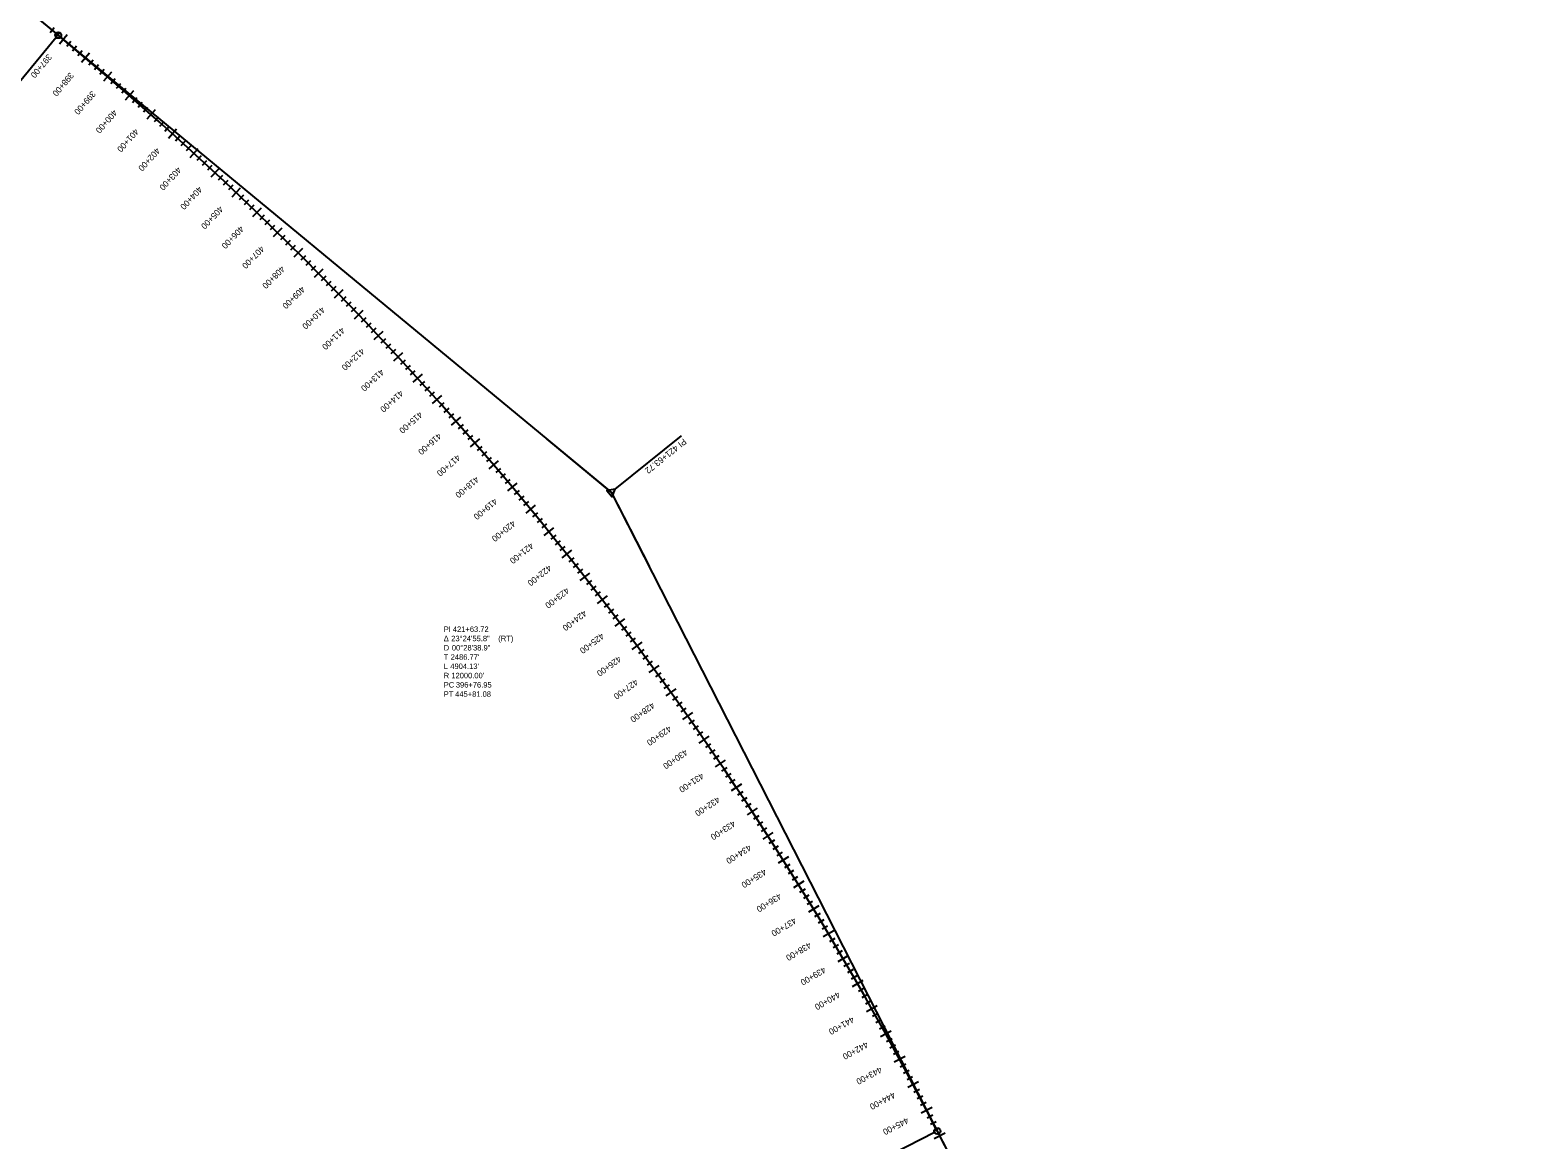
# Model space of a CAD drawing. Extents: x 2823077 to 2858057, y 1248786 to 1289821.
# Drawn here: x 2851223 to 2856449, y 1260299 to 1264146 of the extents above; entities that cross this region are included whole.
import ezdxf

# ---------------------------------------------------------------- set-up
doc = ezdxf.new("R2010")
doc.units = 0
for name, color, linetype in [('_CIVIL_CONSTRUCTION', 7, 'Continuous'), ('Default', 7, 'Continuous'), ('TL_Earth Shoulder Sub', 7, 'Continuous'), ('TL_End Condition Hinge', 7, 'Continuous'), ('TL_Pavement Centerline Sub', 7, 'Continuous'), ('TL_Pavement Edge Sub', 7, 'Continuous'), ('TL_Shoulder Edge', 7, 'Continuous'), ('TL_Shoulder Edge Sub', 7, 'Continuous')]:
    doc.layers.add(name, color=color, linetype=linetype)

msp = doc.modelspace()

# ---------------------------------------------------------------- linework, layer by layer
at = {"layer": '_CIVIL_CONSTRUCTION'}
for p, q in [((2848863.9, 1266157.9), (2851320.6, 1264128.2)), ((2854367.5, 1260328.9), (2856449.3, 1256246.9))]:
    msp.add_line(p, q, dxfattribs=at)
msp.add_arc((2843677.4, 1254877.2), 12000, 27.02082, 50.43633, dxfattribs=at)
at = {"layer": 'Default'}
for p, q in [((2848475.1, 1266479.2), (2853237.7, 1262544.3)), ((2853237.7, 1262544.3), (2855418.4, 1258268.3))]:
    msp.add_line(p, q, dxfattribs=at)
msp.add_arc((2843677.4, 1254877.2), 12000, 27.02082, 50.43633, dxfattribs=at)
msp.add_arc((2843677.4, 1254877.2), 12000, 27.02082, 50.43633, dxfattribs=at)
msp.add_arc((2843677.4, 1254877.2), 12000, 27.02082, 50.43633, dxfattribs=at)
msp.add_arc((2843677.4, 1254877.2), 12000, 27.02082, 50.43633, dxfattribs=at)
at = {"layer": 'TL_Earth Shoulder Sub'}
for p, q in [((2851320.6, 1264128.2), (2851320.6, 1264128.2)), ((2853481.1, 1262739.4), (2853481.1, 1262739.4)), ((2853237.7, 1262544.3), (2853237.7, 1262544.3)), ((2854367.5, 1260328.9), (2854367.5, 1260328.9))]:
    msp.add_line(p, q, dxfattribs=at)
for centre in [(2851320.6, 1264128.2), (2854367.5, 1260328.9)]:
    msp.add_circle(centre, 10.7, dxfattribs=at)
at = {"layer": 'TL_Pavement Centerline Sub'}
for p, q in [((2851352, 1264129.9), (2851324.9, 1264097.2)), ((2851428.9, 1264065.6), (2851401.5, 1264033.2)), ((2851505.2, 1264000.7), (2851477.5, 1263968.5)), ((2851580.9, 1263935.2), (2851553, 1263903.2)), ((2851656.1, 1263869), (2851627.9, 1263837.2)), ((2851730.8, 1263802.2), (2851702.3, 1263770.7)), ((2851804.9, 1263734.8), (2851776.2, 1263703.5)), ((2851878.4, 1263666.7), (2851849.4, 1263635.7)), ((2851951.4, 1263598.1), (2851922.1, 1263567.3)), ((2852023.7, 1263528.8), (2851994.3, 1263498.3)), ((2852095.6, 1263459), (2852065.8, 1263428.7)), ((2852166.8, 1263388.5), (2852136.8, 1263358.5)), ((2852237.4, 1263317.5), (2852207.2, 1263287.7)), ((2852307.4, 1263245.9), (2852277, 1263216.3)), ((2852376.9, 1263173.7), (2852346.1, 1263144.3)), ((2852445.7, 1263100.9), (2852414.7, 1263071.8)), ((2852513.9, 1263027.5), (2852482.7, 1262998.7)), ((2852581.6, 1262953.6), (2852550.1, 1262925.1)), ((2852648.6, 1262879.1), (2852616.9, 1262850.9)), ((2852714.9, 1262804.1), (2852683, 1262776.1)), ((2852780.7, 1262728.5), (2852748.5, 1262700.8)), ((2852845.8, 1262652.4), (2852813.4, 1262624.9)), ((2852910.3, 1262575.7), (2852877.6, 1262548.5)), ((2852974.1, 1262498.5), (2852941.2, 1262471.6)), ((2853037.3, 1262420.8), (2853004.2, 1262394.1)), ((2853099.8, 1262342.5), (2853066.5, 1262316.1)), ((2853161.7, 1262263.7), (2853128.2, 1262237.6)), ((2853222.9, 1262184.4), (2853189.2, 1262158.6)), ((2853283.5, 1262104.6), (2853249.5, 1262079.1)), ((2853343.4, 1262024.3), (2853309.2, 1261999.1)), ((2853402.6, 1261943.5), (2853368.2, 1261918.6)), ((2853461.1, 1261862.2), (2853426.6, 1261837.6)), ((2853519, 1261780.5), (2853484.2, 1261756.1)), ((2853576.2, 1261698.2), (2853541.2, 1261674.1)), ((2853632.7, 1261615.5), (2853597.5, 1261591.7)), ((2853688.5, 1261532.3), (2853653.1, 1261508.8)), ((2853743.6, 1261448.6), (2853708, 1261425.4)), ((2853798, 1261364.5), (2853762.3, 1261341.6)), ((2853851.7, 1261280), (2853815.8, 1261257.3)), ((2853904.7, 1261195), (2853868.6, 1261172.6)), ((2853957, 1261109.5), (2853920.7, 1261087.5)), ((2854008.6, 1261023.6), (2853972.1, 1261001.9)), ((2854059.5, 1260937.3), (2854022.8, 1260915.9)), ((2854109.6, 1260850.6), (2854072.7, 1260829.5)), ((2854159, 1260763.5), (2854122, 1260742.7)), ((2854207.7, 1260675.9), (2854170.5, 1260655.4)), ((2854255.7, 1260588), (2854218.3, 1260567.8)), ((2854302.9, 1260499.6), (2854265.3, 1260479.7)), ((2854349.4, 1260410.9), (2854311.7, 1260391.3)), ((2854395.1, 1260321.8), (2854357.3, 1260302.5))]:
    msp.add_line(p, q, dxfattribs=at)
at = {"layer": 'TL_Pavement Edge Sub'}
for p, q in [((2851306.9, 1264153.8), (2851292.8, 1264136.8)), ((2851326.2, 1264137.9), (2851312.1, 1264120.9)), ((2851364.7, 1264106), (2851350.5, 1264089)), ((2851383.9, 1264089.9), (2851369.7, 1264073)), ((2851403.1, 1264073.9), (2851388.9, 1264057)), ((2851441.3, 1264041.6), (2851427, 1264024.7)), ((2851460.4, 1264025.4), (2851446.1, 1264008.6)), ((2851479.4, 1264009.2), (2851465.1, 1263992.4)), ((2851517.4, 1263976.6), (2851503, 1263959.8)), ((2851536.4, 1263960.2), (2851521.9, 1263943.5)), ((2851555.3, 1263943.8), (2851540.8, 1263927.2)), ((2851593, 1263910.9), (2851578.4, 1263894.3)), ((2851611.8, 1263894.4), (2851597.2, 1263877.8)), ((2851630.5, 1263877.9), (2851615.9, 1263861.3)), ((2851668, 1263844.6), (2851653.3, 1263828.2)), ((2851686.6, 1263828), (2851671.9, 1263811.5)), ((2851705.3, 1263811.3), (2851690.5, 1263794.9)), ((2851742.4, 1263777.7), (2851727.6, 1263761.4)), ((2851760.9, 1263760.9), (2851746.1, 1263744.6)), ((2851779.4, 1263744.1), (2851764.5, 1263727.8)), ((2851816.3, 1263710.2), (2851801.4, 1263694)), ((2851834.7, 1263693.3), (2851819.7, 1263677)), ((2851853, 1263676.2), (2851838, 1263660.1)), ((2851889.6, 1263642.1), (2851874.5, 1263626)), ((2851907.9, 1263625), (2851892.8, 1263608.9)), ((2851926.1, 1263607.8), (2851910.9, 1263591.8)), ((2851962.4, 1263573.4), (2851947.2, 1263557.4)), ((2851980.5, 1263556.1), (2851965.2, 1263540.1)), ((2851998.6, 1263538.8), (2851983.3, 1263522.8)), ((2852034.6, 1263504), (2852019.2, 1263488.2)), ((2852052.5, 1263486.6), (2852037.1, 1263470.8)), ((2852070.4, 1263469.1), (2852055, 1263453.3)), ((2852106.2, 1263434.1), (2852090.7, 1263418.3)), ((2852124, 1263416.5), (2852108.5, 1263400.8)), ((2852141.8, 1263398.9), (2852126.2, 1263383.2)), ((2852177.2, 1263363.5), (2852161.6, 1263347.9)), ((2852194.8, 1263345.8), (2852179.2, 1263330.2)), ((2852212.5, 1263328.1), (2852196.8, 1263312.5)), ((2852247.6, 1263292.4), (2852231.9, 1263276.9)), ((2852265.1, 1263274.5), (2852249.3, 1263259.1)), ((2852282.6, 1263256.6), (2852266.8, 1263241.2)), ((2852317.4, 1263220.7), (2852301.6, 1263205.4)), ((2852334.8, 1263202.7), (2852318.9, 1263187.4)), ((2852352.1, 1263184.6), (2852336.2, 1263169.4)), ((2852386.7, 1263148.4), (2852370.7, 1263133.2)), ((2852403.9, 1263130.3), (2852387.8, 1263115.1)), ((2852421.1, 1263112.1), (2852405, 1263096.9)), ((2852455.3, 1263075.6), (2852439.2, 1263060.5)), ((2852472.4, 1263057.2), (2852456.2, 1263042.2)), ((2852489.4, 1263038.9), (2852473.2, 1263023.9)), ((2852523.3, 1263002.1), (2852507, 1262987.2)), ((2852540.2, 1262983.7), (2852523.9, 1262968.8)), ((2852557.1, 1262965.2), (2852540.8, 1262950.3)), ((2852590.7, 1262928.1), (2852574.3, 1262913.3)), ((2852607.5, 1262909.5), (2852591, 1262894.8)), ((2852624.2, 1262890.9), (2852607.7, 1262876.2)), ((2852657.5, 1262853.6), (2852641, 1262838.9)), ((2852674.1, 1262834.8), (2852657.5, 1262820.2)), ((2852690.6, 1262816.1), (2852674.1, 1262801.5)), ((2852723.6, 1262778.5), (2852707, 1262763.9)), ((2852740.1, 1262759.6), (2852723.4, 1262745.1)), ((2852756.5, 1262740.7), (2852739.8, 1262726.2)), ((2852789.2, 1262702.8), (2852772.4, 1262688.4)), ((2852805.5, 1262683.8), (2852788.7, 1262669.4)), ((2852821.7, 1262664.8), (2852804.9, 1262650.4)), ((2852854.1, 1262626.6), (2852837.2, 1262612.3)), ((2852870.2, 1262607.5), (2852853.3, 1262593.2)), ((2852886.3, 1262588.3), (2852869.4, 1262574.1)), ((2852918.3, 1262549.9), (2852901.3, 1262535.8)), ((2852934.3, 1262530.6), (2852917.3, 1262516.5)), ((2852950.2, 1262511.3), (2852933.2, 1262497.3)), ((2852981.9, 1262472.6), (2852964.8, 1262458.6)), ((2852997.8, 1262453.2), (2852980.6, 1262439.3)), ((2853013.5, 1262433.7), (2852996.4, 1262419.9)), ((2853044.9, 1262394.8), (2853027.7, 1262381)), ((2853060.6, 1262375.2), (2853043.3, 1262361.5)), ((2853076.2, 1262355.7), (2853058.9, 1262341.9)), ((2853107.2, 1262316.5), (2853089.9, 1262302.8)), ((2853122.7, 1262296.8), (2853105.4, 1262283.2)), ((2853138.2, 1262277.1), (2853120.8, 1262263.5)), ((2853168.9, 1262237.6), (2853151.5, 1262224.1)), ((2853184.2, 1262217.8), (2853166.7, 1262204.3)), ((2853199.5, 1262198), (2853182, 1262184.5)), ((2853229.9, 1262158.3), (2853212.4, 1262144.9)), ((2853245.1, 1262138.4), (2853227.5, 1262125)), ((2853260.2, 1262118.4), (2853242.6, 1262105.1)), ((2853290.3, 1262078.4), (2853272.6, 1262065.2)), ((2853305.2, 1262058.4), (2853287.5, 1262045.2)), ((2853320.2, 1262038.3), (2853302.5, 1262025.1)), ((2853349.9, 1261998.1), (2853332.2, 1261985)), ((2853364.7, 1261977.9), (2853346.9, 1261964.8)), ((2853379.5, 1261957.7), (2853361.7, 1261944.7)), ((2853408.9, 1261917.2), (2853391, 1261904.3)), ((2853423.6, 1261896.9), (2853405.7, 1261884)), ((2853438.2, 1261876.6), (2853420.2, 1261863.7)), ((2853467.3, 1261835.9), (2853449.3, 1261823.1)), ((2853481.7, 1261815.5), (2853463.7, 1261802.7)), ((2853496.2, 1261795), (2853478.1, 1261782.3)), ((2853524.9, 1261754), (2853506.8, 1261741.4)), ((2853539.2, 1261733.5), (2853521.1, 1261720.9)), ((2853553.5, 1261713), (2853535.3, 1261700.4)), ((2853581.9, 1261671.7), (2853563.7, 1261659.3)), ((2853596, 1261651.1), (2853577.8, 1261638.6)), ((2853610.1, 1261630.4), (2853591.8, 1261618)), ((2853638.2, 1261589), (2853619.8, 1261576.6)), ((2853652.1, 1261568.2), (2853633.8, 1261555.9)), ((2853666, 1261547.4), (2853647.7, 1261535.1)), ((2853693.7, 1261505.7), (2853675.3, 1261493.5)), ((2853707.5, 1261484.8), (2853689.1, 1261472.7)), ((2853721.3, 1261463.9), (2853702.8, 1261451.8)), ((2853748.6, 1261422), (2853730.1, 1261410)), ((2853762.2, 1261401), (2853743.7, 1261389)), ((2853775.8, 1261380), (2853757.3, 1261368.1)), ((2853802.8, 1261337.9), (2853784.2, 1261326)), ((2853816.3, 1261316.8), (2853797.6, 1261304.9)), ((2853829.7, 1261295.6), (2853811, 1261283.8)), ((2853856.3, 1261253.3), (2853837.6, 1261241.6)), ((2853869.6, 1261232.1), (2853850.8, 1261220.4)), ((2853882.8, 1261210.8), (2853864, 1261199.2)), ((2853909.1, 1261168.2), (2853890.3, 1261156.7)), ((2853922.2, 1261146.9), (2853903.3, 1261135.4)), ((2853935.2, 1261125.5), (2853916.4, 1261114.1)), ((2853961.2, 1261082.8), (2853942.3, 1261071.3)), ((2853974.1, 1261061.3), (2853955.1, 1261049.9)), ((2853986.9, 1261039.8), (2853968, 1261028.5)), ((2854012.5, 1260996.8), (2853993.5, 1260985.6)), ((2854025.2, 1260975.3), (2854006.2, 1260964.1)), ((2854037.9, 1260953.7), (2854018.9, 1260942.6)), ((2854063.2, 1260910.5), (2854044.1, 1260899.4)), ((2854075.7, 1260888.9), (2854056.6, 1260877.8)), ((2854088.2, 1260867.2), (2854069.1, 1260856.2)), ((2854113.1, 1260823.7), (2854093.9, 1260812.8)), ((2854125.4, 1260802), (2854106.2, 1260791.1)), ((2854137.8, 1260780.2), (2854118.5, 1260769.4)), ((2854162.3, 1260736.6), (2854143, 1260725.8)), ((2854174.4, 1260714.7), (2854155.1, 1260704)), ((2854186.6, 1260692.8), (2854167.3, 1260682.1)), ((2854210.7, 1260649), (2854191.4, 1260638.4)), ((2854222.7, 1260627), (2854203.3, 1260616.5)), ((2854234.7, 1260605.1), (2854215.3, 1260594.5)), ((2854258.5, 1260561), (2854239, 1260550.6)), ((2854270.3, 1260539), (2854250.8, 1260528.6)), ((2854282, 1260516.9), (2854262.6, 1260506.5)), ((2854305.5, 1260472.7), (2854285.9, 1260462.4)), ((2854317.1, 1260450.5), (2854297.5, 1260440.3)), ((2854328.7, 1260428.3), (2854309.1, 1260418.1)), ((2854351.7, 1260383.9), (2854332.1, 1260373.8)), ((2854363.2, 1260361.6), (2854343.5, 1260351.6)), ((2854374.6, 1260339.4), (2854354.9, 1260329.3))]:
    msp.add_line(p, q, dxfattribs=at)
at = {"layer": 'TL_Shoulder Edge'}
for p, q in [((2851313.8, 1264119.9), (2851030.2, 1263776.6)), ((2853237.7, 1262544.3), (2853015.7, 1262727.7)), ((2853250.8, 1262554.8), (2853481.1, 1262739.4)), ((2853237.7, 1262544.3), (2853368.6, 1262287.7)), ((2854358, 1260324.1), (2853961.3, 1260121.8))]:
    msp.add_line(p, q, dxfattribs=at)
msp.add_lwpolyline([(2853250.7, 1262554.7), (2853222.2, 1262550.3), (2853240.2, 1262527.8)], close=True, dxfattribs=at)

# ---------------------------------------------------------------- texts
at = {"layer": 'TL_Earth Shoulder Sub'}
for s, p in [('PI ', (2853487.4, 1262731.6)), ('421+63.72', (2853459.3, 1262709.1))]:
    msp.add_text(s, height=21.6, rotation=218.7286, dxfattribs=at).set_placement(p)
at = {"layer": 'TL_End Condition Hinge'}
for s, rotation, p in [('397+00', 230.3263, (2851284.2, 1264064.8)), ('398+00', 229.8488, (2851360.5, 1264001.1)), ('399+00', 229.3713, (2851436.3, 1263936.8)), ('400+00', 228.8939, (2851511.5, 1263871.8)), ('401+00', 228.4164, (2851586.2, 1263806.2)), ('402+00', 227.9389, (2851660.3, 1263740)), ('403+00', 227.4615, (2851733.9, 1263673.2)), ('404+00', 226.984, (2851806.9, 1263605.7)), ('405+00', 226.5065, (2851879.4, 1263537.7)), ('406+00', 226.0291, (2851951.3, 1263469)), ('407+00', 225.5516, (2852022.6, 1263399.8)), ('408+00', 225.0741, (2852093.3, 1263329.9)), ('409+00', 224.5967, (2852163.5, 1263259.5)), ('410+00', 224.1192, (2852233, 1263188.5)), ('411+00', 223.6417, (2852302, 1263116.9)), ('412+00', 223.1643, (2852370.4, 1263044.8)), ('413+00', 222.6868, (2852438.1, 1262972)), ('414+00', 222.2094, (2852505.3, 1262898.8)), ('415+00', 221.7319, (2852571.8, 1262824.9)), ('416+00', 221.2544, (2852637.7, 1262750.5)), ('417+00', 220.777, (2852703, 1262675.6)), ('418+00', 220.2995, (2852767.7, 1262600.1)), ('419+00', 219.822, (2852831.7, 1262524.1)), ('420+00', 219.3446, (2852895.1, 1262447.5)), ('421+00', 218.8671, (2852957.9, 1262370.4)), ('422+00', 218.3896, (2853020, 1262292.9)), ('423+00', 217.9122, (2853081.5, 1262214.7)), ('424+00', 217.4347, (2853142.3, 1262136.1)), ('425+00', 216.9572, (2853202.5, 1262057)), ('426+00', 216.4798, (2853262, 1261977.4)), ('427+00', 216.0023, (2853320.8, 1261897.3)), ('428+00', 215.5248, (2853379, 1261816.6)), ('429+00', 215.0474, (2853436.5, 1261735.6)), ('430+00', 214.5699, (2853493.3, 1261654)), ('431+00', 214.0924, (2853549.4, 1261572)), ('432+00', 213.615, (2853604.9, 1261489.5)), ('433+00', 213.1375, (2853659.6, 1261406.5)), ('434+00', 212.6601, (2853713.7, 1261323.1)), ('435+00', 212.1826, (2853767.1, 1261239.2)), ('436+00', 211.7051, (2853819.7, 1261154.9)), ('437+00', 211.2277, (2853871.7, 1261070.2)), ('438+00', 210.7502, (2853922.9, 1260985)), ('439+00', 210.2727, (2853973.5, 1260899.4)), ('440+00', 209.7953, (2854023.3, 1260813.4)), ('441+00', 209.3178, (2854072.4, 1260727)), ('442+00', 208.8403, (2854120.8, 1260640.2)), ('443+00', 208.3629, (2854168.5, 1260553)), ('444+00', 207.8854, (2854215.4, 1260465.3)), ('445+00', 207.4079, (2854261.6, 1260377.3))]:
    msp.add_text(s, height=21.26, rotation=rotation, dxfattribs=at).set_placement(p)
at = {"layer": 'TL_Shoulder Edge Sub'}
for s, height, p in [('Δ ', 18.9, (2852656.8, 1262027.4)), ('PI ', 18.9, (2852656.8, 1262059.5)), ('23°24\'55.8"', 18.898, (2852682.8, 1262027.4)), ('421+63.72', 18.9, (2852688.4, 1262059.5)), (' (RT)', 18.9, (2852838.6, 1262027.4)), ('T ', 18.9, (2852656.8, 1261963.1)), ('D ', 18.9, (2852656.8, 1261995.2)), ("2486.77'", 18.9, (2852680.9, 1261963.1)), ('00°28\'38.9"', 18.898, (2852685, 1261995.2)), ('L ', 18.9, (2852656.8, 1261931)), ("4904.13'", 18.9, (2852679.5, 1261931)), ('R ', 18.9, (2852656.8, 1261898.9)), ('PC ', 18.9, (2852656.8, 1261866.7)), ("12000.00'", 18.9, (2852683.1, 1261898.9)), ('396+76.95', 18.9, (2852698.8, 1261866.7)), ('PT ', 18.9, (2852656.8, 1261834.6)), ('445+81.08', 18.9, (2852696.5, 1261834.6))]:
    msp.add_text(s, height=height, dxfattribs=at).set_placement(p)

doc.saveas('drawing.dxf')
